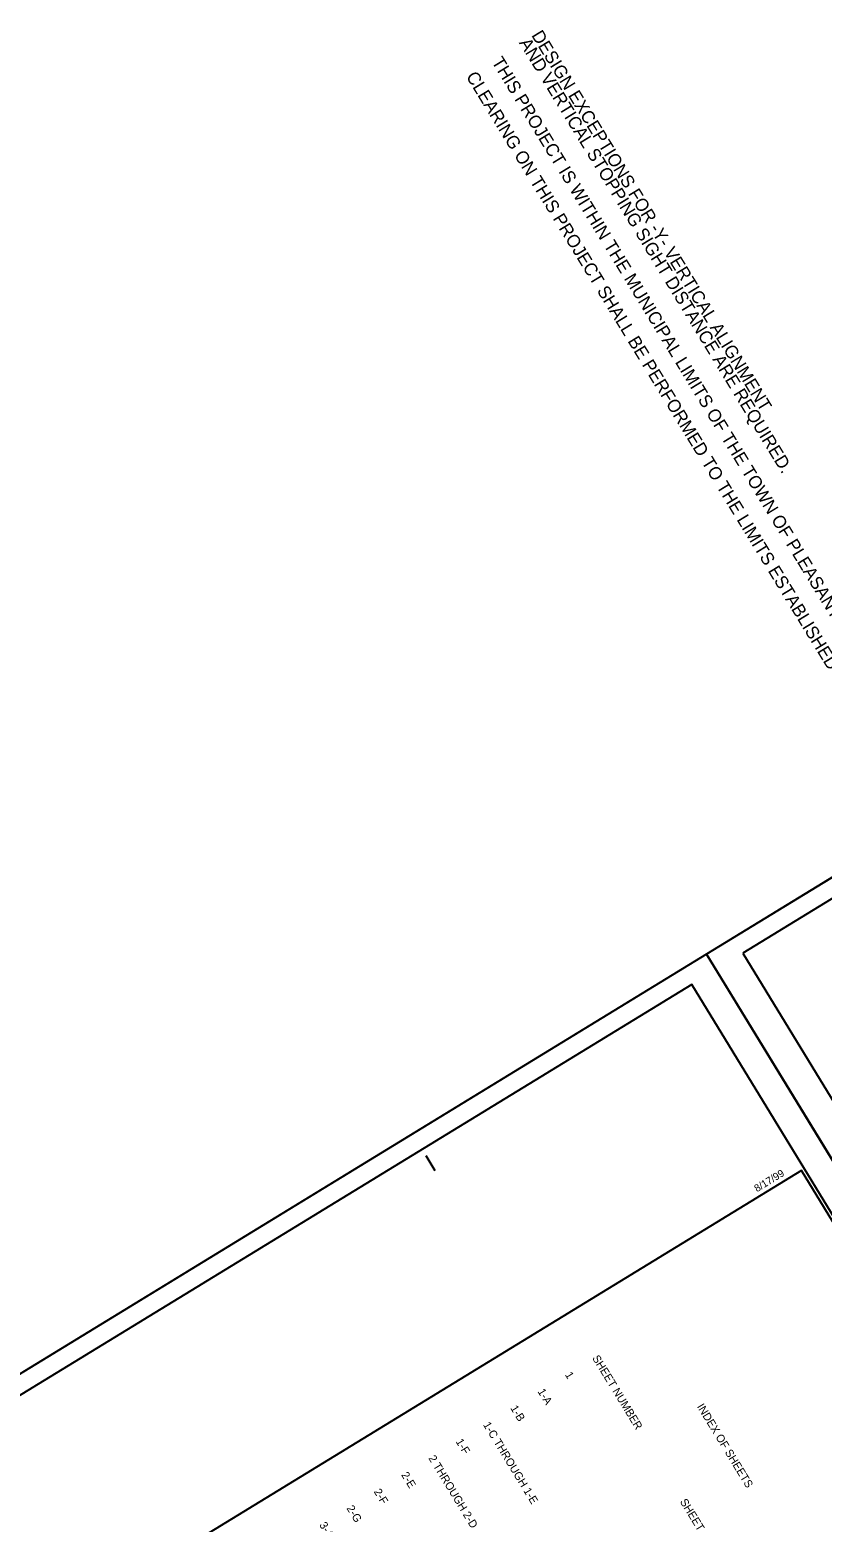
# Model space of a CAD drawing. Extents: x 1750583 to 1791140, y 783580 to 827376.
# Drawn here: x 1765888 to 1772080, y 815720 to 827376 of the extents above; entities that cross this region are included whole.
import ezdxf

# ---------------------------------------------------------------- set-up
doc = ezdxf.new("R2010")
doc.units = 0
for name, color, linetype in [('Prop Dimension Text', 7, 'Continuous'), ('Sheet Cutting Line CELL', 7, 'Continuous'), ('Sheet Plan CELL', 7, 'Continuous'), ('Sheet Plot Border Inside CELL', 7, 'Continuous'), ('Sheet Plot Border Outside CELL', 7, 'Continuous')]:
    doc.layers.add(name, color=color, linetype=linetype)

msp = doc.modelspace()

# ---------------------------------------------------------------- linework, layer by layer
at = {"layer": 'Sheet Cutting Line CELL'}
for p, q in [((1781491, 826460), (1771176, 820157)), ((1771176, 820157), (1760908, 813883)), ((1771176, 820157), (1780825, 804366)), ((1780822, 804371), (1771176, 820157))]:
    msp.add_line(p, q, dxfattribs=at)
at = {"layer": 'Sheet Plan CELL'}
for p, q in [((1768982, 818585), (1769054, 818468)), ((1771919, 818467), (1771919, 818467))]:
    msp.add_line(p, q, dxfattribs=at)
msp.add_lwpolyline([(1780514, 804401), (1771919, 818467), (1762073, 812451), (1770667, 798385)], close=True, dxfattribs=at)
at = {"layer": 'Sheet Plot Border Inside CELL'}
for points in [[(1771461, 820164), (1781009, 804537), (1790904, 810582), (1781355, 826209)], [(1761170, 813876), (1770716, 798253), (1780609, 804298), (1771063, 819921)]]:
    msp.add_lwpolyline(points, close=True, dxfattribs=at)
at = {"layer": 'Sheet Plot Border Outside CELL'}
for points in [[(1791140, 810668), (1781491, 826460), (1771176, 820157), (1780825, 804366)], [(1760908, 813883), (1770554, 798097), (1780822, 804371), (1771176, 820157)]]:
    msp.add_lwpolyline(points, close=True, dxfattribs=at)

# ---------------------------------------------------------------- texts
at = {"layer": 'Prop Dimension Text'}
for s, height, p in [('DESIGN EXCEPTIONS FOR -Y- VERTICAL ALIGNMENT', 100, (1769805, 827334)), ('AND VERTICAL STOPPING SIGHT DISTANCE ARE REQUIRED.', 100, (1769709, 827275)), ('THIS PROJECT IS WITHIN THE MUNICIPAL LIMITS OF THE TOWN OF PLEASANT GARDEN.', 100, (1769494, 827127)), ('CLEARING ON THIS PROJECT SHALL BE PERFORMED TO THE LIMITS ESTABLISHED BY METHOD II.', 100, (1769294, 827013)), ('SHEET NUMBER                            SHEET', 62.5, (1770281, 817002)), ('1', 62.5, (1770068, 816872)), ('1-A', 62.5, (1769854, 816741)), ('1-B', 62.5, (1769641, 816611)), ('INDEX OF SHEETS', 62.5, (1771099, 816623)), ('1-C THROUGH 1-E', 62.5, (1769428, 816481)), ('1-F', 62.5, (1769214, 816350)), ('2 THROUGH 2-D', 62.5, (1769001, 816220)), ('2-E', 62.5, (1768788, 816090)), ('2-F', 62.5, (1768574, 815959)), ('2-G', 62.5, (1768361, 815829)), ('3-A THROUGH 3-C', 62.5, (1768148, 815699))]:
    msp.add_text(s, height=height, rotation=301.4249, dxfattribs=at).set_placement(p)
at = {"layer": 'Sheet Plan CELL'}
msp.add_text('8/17/99', height=57.7, rotation=31.4249, dxfattribs=at).set_placement((1771571, 818296))

doc.saveas('drawing.dxf')
